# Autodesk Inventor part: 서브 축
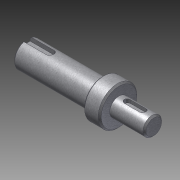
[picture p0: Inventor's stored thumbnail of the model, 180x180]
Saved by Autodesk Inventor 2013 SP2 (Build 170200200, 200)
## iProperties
Created: 2014-10
Part Number: 서브 축
Document SubType Name: Modeling
Designer: KYOUNG IL JANG
Density: 1 g/cm^3
Mass: 19.9624 g
Surface Area: 57.7178 cm^2
Volume: 19.9624 cm^3
Material: 강철, 연강
Author: SeoGD™ [www.esajin.kr]
Revision Number: 1
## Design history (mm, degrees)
sketch "스케치1"
  geometry: L1 (-16.331, 0)-(-98.831, 0); L2 (-16.331, 0)-(-16.331, -6); L3 (-16.331, -6)-(-38.831, -6); L4 (-38.831, -12.5)-(-46.5, -12.5); L5 (-46.5, -8.5)-(-98.831, -8.5); L6 (-98.831, -8.5)-(-98.831, 0); L7 (-46.5, -8.5)-(-46.5, -12.5); L8 (-38.831, -6)-(-38.831, -12.5); L9 (-46.5, 12.249)-(-46.5, -12.249) reference; L10 (-38.831, -17)-(-38.831, 17) reference; 2 further points
  constraints: 17 end point, 4 perpendicular, 2 collinear, 2 parallel, 1 horizontal, 1 midpoint, 1 point on line
  dimensions: "d1" = 12 diameter of L3 L1; "d2" = 25 diameter of L4 L1; "d3" = 17 diameter of L5 L1; "d18" = 22.5 distance of L2.end L3.end; "d20" = 60 distance between parallel lines of L6 L8; "d21" = 7.66872 distance of L4.start L4.end (derived)
revolve "회전1" sketch "스케치1" stored, may be unused: angle "d5" = 90 deg
chamfer "모따기1" distance "d6" = 1; stored, may be unused: second distance "d7" = 2, angle "d8" = 45 deg
node "작업 평면1"
sketch "스케치2"
  geometry: L1 (11.25, 5)-(11.25, -5) reference; L2 (-5.75, -2)-(4.25, -2); L3 (4.25, 2)-(-5.75, 2); A1 r 2 centre (4.25, 0) between (4.25, -2) and (4.25, 2); A2 r 2 centre (-5.75, 0) between (-5.75, 2) and (-5.75, -2); 2 further points
  constraints: 4 end point, 4 point on circle, 4 tangent, 2 centre point, 1 horizontal alignment, 1 midpoint, 1 parallel, 1 perpendicular
  dimensions: "d9" = 4 distance between parallel lines of L2 L3; "d10" = 14 dimension on A1 A2; "d11" = 5 distance edge to line of A1 L1
extrude "돌출1" cut sketch "스케치2" distance "d12" = 2.5; taper "d13" = 0 deg
node "작업 평면2"
sketch "스케치3"
  geometry: L1 (-26.166, -7.5)-(-26.166, 7.5) reference; L2 (-26.166, 2.5)-(-10.666, 2.5); L3 (-10.666, -2.5)-(-26.166, -2.5); A1 r 2.5 centre (-10.666, 0) between (-10.666, -2.5) and (-10.666, 2.5); 2 further points
  constraints: 4 end point, 2 perpendicular, 2 point on circle, 2 point on line, 2 tangent, 1 centre point, 1 horizontal alignment, 1 midpoint
  dimensions: "d14" = 5 distance between parallel lines of L3 L2; "d15" = 18 dimension on A1 L1
extrude "돌출2" cut sketch "스케치3" distance "d16" = 3; taper "d17" = 0 deg
sketch "스케치4"
  geometry: C1 r 12.5 at (0, 0) reference; 1 further point
extrude "돌출3" join sketch "스케치4" distance "d22" = 3; taper "d23" = 0 deg
chamfer "모따기2" distance "d24" = 1; stored, may be unused: second distance "d25" = 2, angle "d26" = 45 deg
node "솔리드1"
node "참조4"
node "참조5"
